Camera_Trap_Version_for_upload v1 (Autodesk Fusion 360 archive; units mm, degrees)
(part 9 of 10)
create_component "CreateComponent7"
create_component "CreateComponent2"
create_component "CreateComponent15"
create_component "CreateComponent3"
create_component "CreateComponent1"
create_component "CreateComponent16"
create_component "CreateComponent8"
create_component "CreateComponent17"
remove_body "RemoveBody4"
create_component "CreateComponent2"
create_component "CreateComponent9"
create_component "CreateComponent4"
create_component "CreateComponent10"
create_component "CreateComponent24"
create_component "CreateComponent25"
create_component "CreateComponent26" sketch "Sketch6"
create_component "CreateComponent27"
create_component "CreateComponent28"
create_component "CreateComponent29"
create_component "CreateComponent30"
create_component "CreateComponent31"
create_component "CreateComponent32"
create_component "CreateComponent33"
create_component "CreateComponent34"
create_component "CreateComponent35"
create_component "CreateComponent36"
create_component "CreateComponent37"
create_component "CreateComponent38"
create_component "CreateComponent39"
create_component "CreateComponent40"
create_component "CreateComponent41"
create_component "CreateComponent42"
create_component "CreateComponent43"
create_component "CreateComponent44"
create_component "CreateComponent45"
create_component "CreateComponent46"
create_component "CreateComponent47"
remove_body "RemoveBody1"
remove_body "RemoveBody2"
remove_body "RemoveBody3"
remove_body "RemoveBody4"
remove_body "RemoveBody5"
remove_body "RemoveBody6"
remove_body "RemoveBody7"
remove_body "RemoveBody8"
remove_body "RemoveBody1"
remove_body "RemoveBody2"
remove_body "RemoveBody3"
remove_body "RemoveBody4"
remove_body "RemoveBody1"
remove_body "RemoveBody1"
remove_body "RemoveBody1"
remove_body "RemoveBody1"
remove_body "RemoveBody1"
remove_body "RemoveBody1"
remove_body "RemoveBody1"
remove_body "RemoveBody1"
remove_body "RemoveBody1"
remove_body "RemoveBody1"
remove_body "RemoveBody1"
create_component "CreateComponent1"
create_component "CreateComponent3"
create_component "CreateComponent49"
create_component "CreateComponent50"
create_component "CreateComponent51"
create_component "CreateComponent52"
create_component "CreateComponent53"
create_component "CreateComponent54"
create_component "CreateComponent55"
create_component "CreateComponent1"
create_component "CreateComponent1"
create_component "CreateComponent2"
create_component "CreateComponent2"
remove_body "RemoveBody1"
create_component "CreateComponent7"
remove_body "RemoveBody2"
create_component "CreateComponent8"
remove_body "RemoveBody3"
create_component "CreateComponent9"
remove_body "RemoveBody4"
create_component "CreateComponent10"
remove_body "RemoveBody5"
remove_body "RemoveBody1"
remove_body "RemoveBody3"
remove_body "RemoveBody1"
remove_body "RemoveBody2"
remove_body "RemoveBody6"
remove_body "RemoveBody2"
create_component "CreateComponent1"
create_component "CreateComponent18"
create_component "CreateComponent9"
create_component "CreateComponent11"
create_component "CreateComponent1"
create_component "CreateComponent2"
remove_body "RemoveBody2"
create_component "CreateComponent13"
create_component "CreateComponent19"
create_component "CreateComponent1"
create_component "CreateComponent56"
remove_body "RemoveBody5"
extrude "Extrude22" cut sketch "Sketch33" profile of C1 C2 C3 C4 against normal blind 9
create_component "CreateComponent2"
create_component "CreateComponent3"
create_component "CreateComponent1"
create_component "CreateComponent5"
create_component "CreateComponent1"
create_component "CreateComponent6"
remove_instance "RemoveInstance1"
named bodies: "Ball_holder", "Screw", "Nut", "Lower_gear", "Mid_gear", "S1_L_Pin", "S1_L_Pin_cutting_tool", "Coupling_testing", "Gear_Holder_Coupling", "S1_paper_holder", "L_ball_bearing", "Right_ball_bearing", "Motor_End", "Motor_sleeve", "348", "340", "342", "344", "343", "interior_motor_holder", "exterior_motor_holder", "upper_pin", "lower_pin", "S2_L_Pin", "S3_L_Pin", "Hanger", "Distance_Test", "Roll_holder", "Roll_holder_34", "Roll_holder_32", "Gear_roll_holder", "Roll_holder_R", "Handle_assembled", "nut_test", "Left_Wall_Cap_Low", "Old_Left_Wall_Cap_Lower", "Left_Wall_Cap_Mid", "Extrusion_Wall", "Extrusion_hole Mid", "Extrusion_hold_Upper", "Front_wall", "OLD_new_below_Lef_Wall_Cap_Upper", "Restraining_Cap", "Sliding_cap", "Motor_holder_base", "Motor_holder_wing", "Left_Wall_Cap_Low (1)", "Right_Wall_Cap_Low (1)", "Handle_Exterior", "Coil", "Cutter_LU_Wall_Cap_", "Cutter_sliding_cap", "Cutter_LL_Wall_Cap", "Motor_test_wall", "Cutter_exterior", "Cutter_interior", "Roof", "Left_wall", "Back_wall", "Right_wall"

design "MicroSD Reader Assembly"
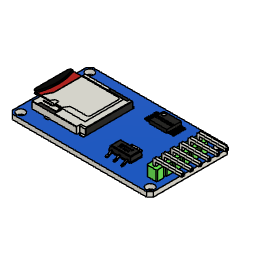
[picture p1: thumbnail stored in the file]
description: Part Number
part number: MicroSD Reader Assembly
part number: sdreader
part number: AMS1117
part number: card sd
base_feature "Base Feature1"
base_feature "Base Feature1"
base_feature "Base Feature1"
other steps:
create_component "CreateComponent1"
create_component "CreateComponent2"
create_component "CreateComponent3"

design "Gears_Motor2" references "9Vcell", "DHT11 module", "Button_Board_II", "Half_Bridge"
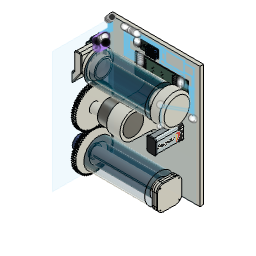
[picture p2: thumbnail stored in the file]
parameter "small_cons_line" = 45
parameter "large_cons_line" = 165
parameter "Roll_Inner_R" = 30
parameter "Roll_Outer_R" = 48
parameter "Roll_length" = 100
parameter "Motor_shaft" = 6
parameter "tube_ball_b" = 8
parameter "Extrusion_ball_b" = 16
parameter "Roll_Holder_major" = 30
parameter "Roll_Holder_minor" = 25
parameter "Holder_rod_bearing" = 8
sketch "Sketch1" plane through (0, 0, 0) normal (1, 0, 0) x axis (0, 1, 0)
sketch "Sketch1" plane through (0, 0, 0) normal (1, 0, 0) x axis (0, 1, 0)
  line L1 (0, 165) -> (0, 0)
  line L2 (0, 45) -> (0, 0)
  point P1 (0, 0)
  point P2 (0, 0)
  point P4 (0, 0)
  point P3 (0, 165)
  point P5 (0, 45)
  coincident P1 P2
  vertical L1
  coincident P1 P4
  parallel L1 L2
  dimension "d1" distance P2 P3 = 165 (= "large_cons_line")
  dimension "d2" distance P4 P5 = 45 (= "small_cons_line")
sketch "Sketch1" plane through (0, 0, 0) normal (1, 0, 0) x axis (0, 1, 0)
  line L1 (0, 105) -> (0, 45)
  line L2 (-11.6, 105) -> (-5.9, 105)
  circle C1 centre (0, 45) radius 24
  circle C2 centre (0, 45) radius 15
  circle C3 centre (0, 165) radius 15
  circle C4 centre (0, 165) radius 24
  circle C5 centre (0, 105) radius 3
  circle C6 centre (0, 105) radius 5.9
  circle C7 centre (0, 165) radius 30
  circle C8 centre (0, 45) radius 30
  circle C9 centre (6.8, 105) radius 18.4
  circle C10 centre (6.8, 105) radius 16.9
  circle C11 centre (0, 105) radius 30
  circle C12 centre (0, 105) radius 8
  point P3 (0, 45)
  point P6 (0, 45)
  point P7 (0, 105)
  point P8 (0, 105)
  point P12 (-5.9, 105)
  point P13 (-11.6, 105)
  concentric C1 C2
  concentric C3 C4
  coincident P3 P6
  vertical L1
  coincident P7 P8
  concentric C5 C6
  concentric C3 C7
  concentric C2 C8
  coincident C6 P12
  horizontal L2
  coincident P13 C9
  concentric C9 C10
  concentric C6 C11
  concentric C5 C12
  dimension "d7" diameter C1 = 48 (= "Roll_Outer_R")
  dimension "d8" diameter C2 = 30 (= "Roll_Inner_R")
  dimension "d9" diameter C3 = 30 (= "Roll_Inner_R")
  dimension "d10" diameter C4 = 48 (= "Roll_Outer_R")
  dimension "d14" distance P6 P7 = 60
  dimension "d16" diameter C5 = 6 (= "Motor_shaft")
  dimension "d17" diameter C6 = 11.8
  dimension "d18" diameter C7 = 60
  dimension "d20" diameter C8 = 60
  dimension "d22" distance P12 P13 = 5.7
  dimension "d23" diameter C9 = 36.8
  dimension "d24" diameter C10 = 33.8
  dimension "d25" diameter C11 = 60
  dimension "d120" diameter C12 = 16
extrude "Extrude1" new body sketch "Sketch1" profile of C1 C2 C3 C4 along normal blind 100 bodies "Lower_Roll", "Upper_Roll"
extrude "Extrude2" new body sketch "Sketch1" profile of C5 along normal blind 13 bodies "Motor_Shaft"
extrude "Extrude3" new body sketch "Sketch1" profile of C5 C6 blind 4 from offset 13 bodies "Shaft_Base"
extrude "Extrude4" new body sketch "Sketch1" profile of C6 C9 C10 blind 18 from offset 17 bodies "Motor_Gear_Box"
extrude "Extrude5" new body sketch "Sketch1" profile of C5 C6 C10 blind 22.5 from offset 35 bodies "Motor_End"
combine "Combine1" bodies "Motor"
sketch "Gear_teeth" plane through (0, 0, 0) normal (0, 0, 1) x axis (1, 0, 0)
  curve K1 (31.9963, -0.4887) -> (29.9991, -0.9267)
  curve K2 (31.9963, 0.4887) -> (29.9991, 0.9267)
  curve K3 (29.9991, -0.9267) -> (29.9983, -0.9266)
  curve K4 (29.9991, 0.9267) -> (29.9983, 0.9266)
  line L1 (29.9983, -0.9266) -> (0, 0)
  line L2 (29.9983, 0.9266) -> (0, 0)
  line L3 (0, 0) -> (0, 0)
  line L4 (0, 0) -> (0, 0)
  arc A1 centre (0, 0) radius 32 clockwise from (31.9963, 0.4887) to (31.9963, -0.4887)
sketch "Gear_Circle" plane through (0, 0, 0) normal (0, 0, 1) x axis (1, 0, 0)
  circle C1 centre (0, 0) radius 29.75
  circle C2 centre (0, 0) radius 8
  circle C3 centre (0, 0) radius 4
  circle C4 centre (0, 0) radius 6
  circle C5 centre (0, 0) radius 11
  concentric C1 C2
  concentric C2 C3
  concentric C1 C4
  concentric C2 C5
  dimension "d121" diameter C2 = 16
  dimension "d154" diameter C3 = 8 (= "tube_ball_b")
  dimension "d157" diameter C4 = 12
  dimension "d158" diameter C5 = 22
extrude "Extrude1" new body sketch "Gear_Circle" profile of C1 along normal blind 3 bodies "Motor_Coupling"
sweep "Sweep1" sketch "Gear_teeth" TwistAngle 1.5 TaperAngle 0
circular_pattern "C-Pattern1" countU 62 TotalAngle 360
combine "Combine1"
work_plane "WorkPlane1" AlongDistance 3
mirror "Mirror1" mirrorStitchTolerance 0.01
combine "Combine2"
sketch "Gear_Label" plane through (0, 0, 0) normal (0, 0, 1) x axis (1, 0, 0)
  curve K1 (83.1636, 0) -> (0, 0)
  curve K2 (83.1636, 3) -> (83.1636, 0)
  curve K3 (0, 3) -> (83.1636, 3)
  curve K4 (0, 0) -> (0, 3)
  perpendicular K1 K2
  parallel K1 K3
  parallel K2 K4
sketch "Gear_teeth" plane through (0, 0, 0) normal (0, 0, 1) x axis (1, 0, 0)
  curve K1 (31.9963, -0.4887) -> (29.9991, -0.9267)
  curve K2 (31.9963, 0.4887) -> (29.9991, 0.9267)
  curve K3 (29.9991, -0.9267) -> (29.9983, -0.9266)
  curve K4 (29.9991, 0.9267) -> (29.9983, 0.9266)
  line L1 (29.9983, -0.9266) -> (0, 0)
  line L2 (29.9983, 0.9266) -> (0, 0)
  line L3 (0, 0) -> (0, 0)
  line L4 (0, 0) -> (0, 0)
  arc A1 centre (0, 0) radius 32 clockwise from (31.9963, 0.4887) to (31.9963, -0.4887)
sketch "Gear_Circle" plane through (0, 0, 0) normal (0, 0, 1) x axis (1, 0, 0)
  circle C1 centre (0, 0) radius 29.75
  circle C2 centre (0, 0) radius 6
  circle C3 centre (0, 0) radius 15
  circle C4 centre (0, 0) radius 12.5
  circle C5 centre (0, 0) radius 20
  concentric C1 C2
  concentric C2 C3
  concentric C1 C4
  concentric C1 C5
  dimension "d102" diameter C2 = 12
  dimension "d115" diameter C3 = 30 (= "Roll_Holder_major")
  dimension "d117" diameter C4 = 25 (= "Roll_Holder_minor")
extrude "Extrude1" new body sketch "Gear_Circle" profile of C1 along normal blind 3 named "d89_1" bodies "Upper_Gear"
sweep "Sweep1" sketch "Gear_teeth" TwistAngle 1.5 named "d95_1" TaperAngle 0 named "d96_1"
circular_pattern "C-Pattern1" countU 62 named "d97_1" TotalAngle 360 named "d98_1"
combine "Combine1"
work_plane "WorkPlane1" AlongDistance 3 named "d99_1"
mirror "Mirror1" mirrorStitchTolerance 0.01 named "d101_1"
combine "Combine2"
sketch "Gear_Label" plane through (0, 0, 0) normal (0, 0, 1) x axis (1, 0, 0)
  curve K1 (83.1636, 0) -> (0, 0)
  curve K2 (83.1636, 3) -> (83.1636, 0)
  curve K3 (0, 3) -> (83.1636, 3)
  curve K4 (0, 0) -> (0, 3)
  perpendicular K1 K2
  parallel K1 K3
  parallel K2 K4
sketch "Sketch1" plane through (0, 0, 0) normal (0, 0, 1) x axis (1, 0, 0)
  curve K1 (31.9963, -0.4887) -> (29.9991, -0.9267)
  curve K2 (31.9963, 0.4887) -> (29.9991, 0.9267)
  curve K3 (29.9991, -0.9267) -> (29.9983, -0.9266)
  curve K4 (29.9991, 0.9267) -> (29.9983, 0.9266)
  line L1 (29.9983, -0.9266) -> (0, 0)
  line L2 (29.9983, 0.9266) -> (0, 0)
  line L3 (0, 0) -> (0, 0)
  line L4 (0, 0) -> (0, 0)
  arc A1 centre (0, 0) radius 32 clockwise from (31.9963, 0.4887) to (31.9963, -0.4887)
sketch "Sketch2" plane through (0, 0, 0) normal (0, 0, 1) x axis (1, 0, 0)
  circle C1 centre (0, 0) radius 29.75
  circle C2 centre (0, 0) radius 10
  circle C3 centre (0, 0) radius 4
  circle C4 centre (0, 0) radius 11
  concentric C1 C2
  concentric C2 C3
  concentric C2 C4
  dimension "d126" diameter C2 = 20
  dimension "d151" diameter C3 = 8
  dimension "d162" diameter C4 = 22
extrude "Extrude1" new body sketch "Sketch2" profile of C1 along normal blind 3 named "d89_2" bodies "Upper_Gear"
sweep "Sweep1" sketch "Sketch1" TwistAngle 1.5 named "d95_2" TaperAngle 0 named "d96_2"
circular_pattern "C-Pattern1" countU 62 named "d97_2" TotalAngle 360 named "d98_2"
combine "Combine1"
work_plane "WorkPlane1" AlongDistance 3 named "d99_2"
mirror "Mirror1" mirrorStitchTolerance 0.01 named "d101_2"
combine "Combine2"
sketch "Sketch3" plane through (0, 0, 0) normal (0, 0, 1) x axis (1, 0, 0)
  curve K1 (83.1636, 0) -> (0, 0)
  curve K2 (83.1636, 3) -> (83.1636, 0)
  curve K3 (0, 3) -> (83.1636, 3)
  curve K4 (0, 0) -> (0, 3)
  perpendicular K1 K2
  parallel K1 K3
  parallel K2 K4
extrude "Extrude2" new body sketch "Gear_Circle" profile of C2 along a picked direction blind 8 bodies "Nut_stopper_L"
position "Position1"
sketch "Sketch4" plane through (0, 0, 8) normal (0, 0, 1) x axis (-1, 0, 0)
  circle C1 centre (0, 0) radius 6
  circle C2 centre (0, 0) radius 4
  circle C3 centre (0, 0) radius 11
  circle C4 centre (0, 0) radius 4
  point P1 (0, 0)
  point P3 (0, 0)
  coincident P1 P3
  concentric C2 C3
  concentric C2 C4
  dimension "d105" diameter C2 = 8 (= "tube_ball_b")
  dimension "d110" diameter C3 = 22
  dimension "d111" diameter C4 = 8
extrude "Extrude3" new body sketch "Sketch4" profile of C2 C4 along a picked direction blind 16 (= "Extrusion_ball_b") bodies "Gear_cylinder_L"
extrude "Extrude4" new body sketch "Sketch4" along a picked direction blind 7 bodies "Ball_Bearing_L"
extrude "Extrude5" new body sketch "Gear_Circle" profile of C3 C4 along a picked direction blind -10 from offset -5 bodies "Cilinder_holder_L"
position "Position2"
extrude "Extrude2" add sketch "Gear_Circle" profile of C2 C3 C4 along a picked direction blind -16.5
combine "Combine4"
extrude "Extrude6" new body sketch "Gear_Circle" profile of C2 C3 C4 C5 along a picked direction blind -7 bodies "Cilinder_stopper_L"
move "Move1"
sketch "Sketch2" plane through (0, 0, 0) normal (0, 1, 0) x axis (0, 0, 1)
extrude "Extrude2" new body sketch "Sketch2" profile of C2 along a picked direction blind -2 bodies "Base"
sketch "Profile_bar_upper_axes" plane through (0, 0, 0) normal (0, 1, 0) x axis (1, 0, 0)
  line L1 (5, -157) -> (5, -177)
  line L2 (3, -177) -> (3, -157)
  line L3 (5, -177) -> (3, -177)
  line L4 (5, -157) -> (3, -157)
  line L5 (5, -167) -> (106, -167)
  line L6 (116, -167) -> (5, -167)
  line L7 (116, -159) -> (116, -167)
  line L8 (5, -159) -> (116, -159)
  line L9 (5, -159) -> (5, -167)
  line L10 (111, -168) -> (10, -168)
  line L11 (111, -166) -> (111, -168)
  line L12 (10, -166) -> (111, -166)
  line L13 (10, -168) -> (10, -166)
  point P6 (5, -167)
  point P10 (5, -159)
  point P8 (116, -167)
  point P11 (10, -168)
  point P12 (111, -168)
  midpoint L1 P6
  perpendicular L1 L6
  perpendicular L6 L7
  coincident L1 P10
  perpendicular L1 L8
  horizontal L10
  vertical L11
  horizontal L12
  vertical L13
  dimension "d141" distance P6 P8 = 111
  dimension "d143" distance P11 P12 = 101
revolve "Revolve2" sketch "Profile_bar_upper_axes" AlongAngle 360 bodies "Tape_holder"
extrude "Extrude2" new body sketch "Profile_bar_upper_axes" profile of L6 L10 L11 L12 L13 distance 10 bodies "Cutter_slit"
combine "Combine4"
move "Move2"
sketch "Sketch5" plane through (0, 0, -107) normal (0, 0, -1) x axis (1, 0, 0)
  circle C1 centre (2, 0) radius 15
  circle C2 centre (2, 0) radius 24
sketch "Sketch3" plane through (116, 0, 0) normal (1, 0, 0) x axis (0, 1, 0)
  circle C1 centre (0, 167) radius 8
  circle C2 centre (0, 167.5) radius 4
  dimension "d148" diameter C2 = 8 (= "Holder_rod_bearing")
extrude "Extrude3" add sketch "Sketch3" profile of C2 along normal blind 8
move "Move3"
sketch "Sketch4" plane through (116, 0, 0) normal (1, 0, 0) x axis (0, 1, 0)
  circle C1 centre (0, 167.5) radius 4
  circle C2 centre (0, 167) radius 8
extrude "Extrude4" new body sketch "Sketch2" profile of C3 along a picked direction blind 24 bodies "Gear_tube"
extrude "Extrude3" new body sketch "Gear_Circle" profile of C3 along normal blind 24 bodies "Gear_Tube"
extrude "Extrude4" new body sketch "Gear_Circle" profile of C2 C3 C4 C5 blind 7 from offset 17 bodies "Nut"
extrude "Extrude5" new body sketch "Sketch2" profile of C2 C3 C4 along a picked direction blind 7 from offset 17 bodies "Nut_L"
extrude "Extrude6" new body sketch "Sketch2" profile of C2 C3 C4 along a picked direction blind -7 from offset -114 bodies "Nut_R"
extrude "Extrude7" new body sketch "Gear_Circle" profile of C3 C4 along a picked direction blind -10 from offset -97 bodies "Cilinder_holder_R"
sketch "Sketch6" plane through (0, 0, -107) normal (0, 0, -1) x axis (1, 0, 0)
  circle C1 centre (2, 0) radius 15
  circle C2 centre (2, 0) radius 24
  circle C3 centre (0, 0) radius 30
  point P1 (0, 0)
  point P3 (0, 0)
  coincident P1 P3
  dimension "d172" diameter C3 = 60
extrude "Extrude8" add sketch "Sketch6" along a picked direction blind 28
sketch "Sketch5" plane through (138, 0, 0) normal (1, 0, 0) x axis (0, 1, 0)
  circle C1 centre (0, 43) radius 30
sketch "Sketch8" plane through (3, 0, 167) normal (-1, 0, 0) x axis (0, 0, 1)
sketch "Sketch4" plane through (0, 0, -121) normal (0, 0, -1) x axis (1, 0, 0)
  line L1 (-10, -20) -> (10, -20)
  line L2 (-20, 10) -> (-20, -10)
  line L3 (10, 20) -> (-10, 20)
  line L4 (20, -10) -> (20, 10)
  line L5 (-20, 20) -> (20, -20)
  line L6 (20, 20) -> (-20, -20)
  line L7 (-15, 10) -> (-15, -10)
  line L8 (-10, -15) -> (10, -15)
  line L9 (15, -10) -> (15, 10)
  line L10 (10, 15) -> (-10, 15)
  line L11 (0, -24) -> (0, 30)
  circle C1 centre (0, 0) radius 4
  circle C2 centre (0, 0) radius 11
  arc A1 centre (-10, 10) radius 10 clockwise from (-20, 10) to (-10, 20)
  arc A2 centre (10, 10) radius 10 clockwise from (10, 20) to (20, 10)
  arc A3 centre (10, -10) radius 10 clockwise from (20, -10) to (10, -20)
  arc A4 centre (-10, -10) radius 10 clockwise from (-10, -20) to (-20, -10)
  arc A5 centre (-10, 10) radius 5 clockwise from (-15, 10) to (-10, 15)
  arc A6 centre (-10, -10) radius 5 clockwise from (-10, -15) to (-15, -10)
  arc A7 centre (10, -10) radius 5 clockwise from (15, -10) to (10, -15)
  arc A8 centre (10, 10) radius 5 clockwise from (10, 15) to (15, 10)
  circle C3 centre (-15.3852, 15.3852) radius 0.75
  circle C4 centre (15.3852, -15.3852) radius 0.75
  circle C5 centre (15.3852, 15.3852) radius 0.75
  circle C6 centre (-15.3852, -15.3852) radius 0.75
  point P7 (0, 0)
  point P1 (0, 0)
  point P5 (-20, 20)
  point P6 (20, 20)
  point P3 (20, -20)
  point P4 (-20, -20)
  point P32 (-15.3852, 15.3852)
  horizontal L1
  perpendicular L1 L2
  parallel L1 L3
  parallel L2 L4
  coincident L5 P7
  coincident L6 P7
  coincident P1 P7
  coincident P5 L3
  coincident P5 L2
  tangent L3 A1
  tangent L2 A1
  coincident P6 L3
  coincident P6 L4
  tangent L3 A2
  tangent L4 A2
  equal A1 A2
  coincident P3 L4
  coincident P3 L1
  tangent L4 A3
  tangent L1 A3
  equal A1 A3
  coincident P4 L1
  coincident P4 L2
  tangent L1 A4
  tangent L2 A4
  equal A1 A4
  coincident L5 P32
  symmetric L6 C3 C4
  perpendicular L1 L11
  symmetric C3 L11 C5
  symmetric C4 L11 C6
  dimension "d185" distance P5 P6 = 40
  dimension "d186" distance P4 P5 = 40
  dimension "d187" radius A1 = 10
  dimension "d188" = 5
  dimension "d189" diameter C3 = 1.5
extrude "Extrude8" new body sketch "Sketch4" profile of C1 C2 L1 L2 L3 L4 A1 A2 A3 A4 L10 A6 L7 L9 L8 A5 A7 A8 C3 C4 C5 C6 along a picked direction blind 2 bodies "Lid_outer"
extrude "Extrude9" new body sketch "Sketch4" profile of C2 L1 L2 L3 L4 A1 A2 A3 A4 L10 A6 L7 L9 L8 A5 A7 A8 C3 C4 C5 C6 along a picked direction blind -3.5 bodies "Lid_mid"
extrude "Extrude10" new body sketch "Sketch4" profile of C2 L1 L2 L3 L4 A1 A2 A3 A4 L10 A6 L7 L9 L8 A5 A7 A8 C3 C4 C5 C6 along a picked direction blind -3 from offset -3.5 bodies "Lid_Inner"
move "Move1"
move "Move2"
move "Move4"
move "Move3"
move "Move4"
position "Position3"
work_plane "WorkPlane1" AlongDistance 0
sketch "Sketch3" plane through (-19.6953, 0, 0) normal (-1, 0, 0) x axis (0, -1, 0)
  line L1 (50, 200) -> (-50, 200)
  line L2 (50, 0) -> (50, 200)
  line L3 (-50, 0) -> (50, 0)
  line L4 (-50, 200) -> (-50, 0)
  horizontal L1
  vertical L2
  horizontal L3
  vertical L4
extrude "Extrude1" new body sketch "Sketch3" against normal blind 7 bodies "Wall_L"
move "Move1"
move "Move5"
work_plane "WorkPlane2" AlongDistance 0
sketch "Sketch5" plane through (0, 0, -123) normal (0, 0, -1) x axis (-1, 0, 0)
  line L1 (161.7205, 51.2462) -> (161.7205, -48.7538)
  line L2 (-38.2795, 51.2462) -> (161.7205, 51.2462)
  line L3 (-38.2795, -48.7538) -> (-38.2795, 51.2462)
  line L4 (161.7205, -48.7538) -> (-38.2795, -48.7538)
  line L5 (161.7205, -48.7538) -> (-38.2795, -48.7538)
  line L6 (161.7205, 51.2462) -> (161.7205, -48.7538)
  line L7 (-38.2795, 51.2462) -> (161.7205, 51.2462)
  line L8 (-38.2795, -48.7538) -> (-38.2795, 51.2462)
  point P3 (161.7205, 51.2462)
  point P8 (161.7205, 51.2462)
  point P5 (-38.2795, -48.7538)
  point P6 (-38.2795, -48.7538)
  horizontal L5
  vertical L6
  horizontal L7
  vertical L8
  coincident P3 P8
  coincident P5 P6
work_plane "WorkPlane2" AlongDistance 0
sketch "Right_Wall" plane through (127.3047, 0, 0) normal (1, 0, 0) x axis (0, 1, 0)
  line L1 (50, 0) -> (-50, 0)
  line L2 (50, 200) -> (50, 0)
  line L3 (-50, 200) -> (50, 200)
  line L4 (-50, 0) -> (-50, 200)
  line L5 (50, 200) -> (-50, 200)
  line L6 (50, 0) -> (50, 200)
  line L7 (-50, 0) -> (50, 0)
  line L8 (-50, 200) -> (-50, 0)
  point P3 (50, 0)
  point P8 (50, 0)
  point P5 (-50, 200)
  point P6 (-50, 200)
  horizontal L5
  vertical L6
  horizontal L7
  vertical L8
  coincident P3 P8
  coincident P5 P6
extrude "Extrude2" new body sketch "Right_Wall" blind -7 from offset -0.5 bodies "Wall_R"
sketch "Sketch9" plane through (60.5, 6.8, 105) normal (1, 0, 0) x axis (0, 1, 0)
work_plane "WorkPlane1" AlongDistance 0
sketch "Sketch2" plane through (57.5, 0, 0) normal (1, 0, 0) x axis (0, 1, 0)
  line L1 (50, 0) -> (50, 200)
  line L2 (50, 200) -> (-50, 200)
  line L3 (-50, 200) -> (-50, 0)
  line L4 (-50, 0) -> (50, 0)
  line L5 (6.8, 130) -> (6.8, 105)
  line L6 (23.7, 105) -> (6.8, 105)
  line L7 (35.3818, 127.6278) -> (6.8, 126.9)
  line L8 (50, 200) -> (-50, 200)
  line L9 (50, 142.6229) -> (50, 200)
  line L10 (-50, 0) -> (50, 0)
  line L11 (-50, 200) -> (-50, 0)
  line L12 (35.3818, 82.3722) -> (6.8, 83.1)
  circle C1 centre (6.8, 105) radius 16.9
  circle C2 centre (6.8, 105) radius 21.9
  arc A1 centre (35, 142.6229) radius 15 clockwise from (50, 142.6229) to (35.3818, 127.6278)
  arc A2 centre (35, 67.3771) radius 15 clockwise from (35.3818, 82.3722) to (50, 67.3771)
  point P2 (6.8, 105)
  point P7 (6.8, 105)
  point P10 (6.8, 105)
  point P11 (23.7, 105)
  point P12 (6.8, 126.9)
  point P4 (50, 0)
  point P15 (50, 0)
  point P5 (-50, 200)
  point P13 (-50, 200)
  point P20 (6.8, 83.1)
  point P17 (35.3818, 127.6278)
  point P21 (35.3818, 82.3722)
  point P18 (50, 142.6229)
  point P23 (50, 67.3771)
  coincident P2 P7
  vertical L5
  coincident P2 P10
  coincident C1 P11
  perpendicular L5 L6
  coincident L5 P12
  coincident C2 P12
  horizontal L8
  vertical L9
  horizontal L10
  vertical L11
  coincident P4 P15
  coincident P5 P13
  coincident P15 L9
  tangent L7 A1
  tangent L9 A1
  symmetric L6 P12 P20
  symmetric L6 P17 P21
  symmetric L6 P18 P23
  symmetric L6 A1 A2
  dimension "d211" = 5
  dimension "d218" radius A1 = 15
extrude "Extrude6" new body sketch "Sketch2" profile of C1 L1 C2 L7 A1 L12 A2 against normal blind 22 bodies "Motor_holder"
sketch "Sketch10" plane through (60.5, 0, 0) normal (1, 0, 0) x axis (0, 1, 0)
work_plane "WorkPlane5" AlongDistance 0
sketch "Sketch6" plane through (0, 50, 0) normal (0, 1, 0) x axis (1, 0, 0)
  line L1 (119.8047, 0) -> (126.8047, 0)
  line L2 (119.8047, -200) -> (119.8047, 0)
  line L3 (126.8047, -200) -> (119.8047, -200)
  line L4 (-22.6953, -200) -> (-22.6953, 0)
  line L5 (-15.6953, -200) -> (-22.6953, -200)
  line L6 (-15.6953, 0) -> (-15.6953, -200)
  line L7 (-22.6953, 0) -> (-15.6953, 0)
  line L8 (-22.6953, -200) -> (126.8047, -200)
  line L9 (-22.6953, 0) -> (-22.6953, -200)
  line L10 (126.8047, 0) -> (-22.6953, 0)
  point P6 (-22.6953, 0)
  point P12 (-22.6953, 0)
  point P2 (126.8047, -200)
  point P10 (126.8047, -200)
  horizontal L8
  vertical L9
  horizontal L10
  coincident P6 P12
  coincident P2 P10
extrude "Extrude4" new body sketch "Sketch6" along normal blind 6 bodies "Wall_Back"
sketch "Sketch11" plane through (138, 0, 0) normal (1, 0, 0) x axis (0, 1, 0)
  line L1 (0, 13) -> (0, 73)
  line L2 (29.9333, 41) -> (0, 41)
  line L3 (-29.9333, 41) -> (0, 41)
  line L4 (0, 41) -> (0, 73)
  line L5 (0, 73) -> (0, 41)
  line L6 (-29.9333, 41) -> (0, 41)
  circle C1 centre (0, 43) radius 30
  point P3 (0, 73)
  point P4 (0, 13)
  point P5 (0, 41)
  point P6 (29.9333, 41)
  point P7 (-29.9333, 41)
  coincident C1 P3
  coincident C1 P4
  vertical L1
  coincident L1 P5
  coincident C1 P6
  perpendicular L1 L2
  coincident C1 P7
  perpendicular L1 L3
sketch "Sketch8" plane through (0, 0, -135) normal (0, 0, -1) x axis (1, 0, 0)
  line L1 (-21.7198, 3.5) -> (-3.5, 3.5)
  line L2 (-30, 3.5) -> (-29.7951, 3.5)
  line L3 (-3.5, 29.7951) -> (-3.5, 30)
  line L4 (-3.5, 3.5) -> (-3.5, 21.7198)
  line L5 (0, 30) -> (0, -30)
  line L6 (30, 0) -> (-30, 0)
  line L7 (21.7198, 3.5) -> (3.5, 3.5)
  line L8 (3.5, 3.5) -> (3.5, 21.7198)
  line L9 (-21.7198, -3.5) -> (-3.5, -3.5)
  line L10 (-3.5, -3.5) -> (-3.5, -21.7198)
  line L11 (3.5, -3.5) -> (3.5, -21.7198)
  line L12 (21.7198, -3.5) -> (3.5, -3.5)
  circle C1 centre (0, 0) radius 30
  circle C2 centre (0, 0) radius 30
  arc A1 centre (0, 0) radius 22 clockwise from (-21.7198, 3.5) to (-3.5, 21.7198)
  arc A2 centre (0, 0) radius 22 clockwise from (3.5, 21.7198) to (21.7198, 3.5)
  arc A3 centre (0, 0) radius 22 clockwise from (-3.5, -21.7198) to (-21.7198, -3.5)
  arc A4 centre (0, 0) radius 22 clockwise from (21.7198, -3.5) to (3.5, -21.7198)
  point P1 (0, 0)
  point P3 (0, 0)
  point P9 (-29.7951, 3.5)
  point P10 (-3.5, 21.7198)
  point P11 (-3.5, 29.7951)
  point P12 (0, -30)
  point P13 (0, 30)
  point P14 (-30, 0)
  point P15 (30, 0)
  point P5 (-3.5, 3.5)
  point P16 (3.5, 3.5)
  point P8 (-21.7198, 3.5)
  point P17 (21.7198, 3.5)
  point P18 (3.5, 21.7198)
  point P20 (-3.5, -3.5)
  point P21 (-21.7198, -3.5)
  point P22 (-3.5, -21.7198)
  point P25 (3.5, -3.5)
  point P26 (21.7198, -3.5)
  point P24 (3.5, -21.7198)
  coincident P1 P3
  concentric C2 A1
  coincident C1 P9
  collinear L1 L2
  coincident P10 L3
  coincident C1 P11
  collinear L3 L4
  coincident C2 P12
  coincident C2 P13
  vertical L5
  coincident C1 P14
  coincident C1 P15
  horizontal L6
  symmetric P5 L5 P16
  symmetric A1 L5 A2
  symmetric P8 L5 P17
  symmetric P10 L5 P18
  symmetric P5 L6 P20
  symmetric A1 L6 A3
  symmetric P8 L6 P21
  symmetric P10 L6 P22
  symmetric L5 P20 P25
  symmetric L5 P21 P26
  symmetric L5 P22 P24
  symmetric L5 A3 A4
extrude "Extrude10" cut sketch "Sketch8" profile of L2 L4 A1 L7 L8 A2 L9 L10 A3 L11 L12 A4 along a picked direction blind -5
fillet "Fillet1" radius 2
fillet "Fillet2" radius 2
fillet "Fillet3" radius 2
fillet "Fillet4" radius 3
component_insert "Component Insert1"
position "Position4"
sketch "Sketch7" plane through (119.8047, 0, 0) normal (-1, 0, 0) x axis (0, -1, 0)
  line L1 (50, 0) -> (-50, 0)
  line L2 (50, 200) -> (50, 0)
  line L3 (-50, 200) -> (50, 200)
  line L4 (-50, 0) -> (-50, 200)
  line L5 (12, 122.3488) -> (-23.6969, 122.3488)
  line L6 (12, 97.3488) -> (-23.6969, 97.3488)
  line L7 (-33.15, 112.1992) -> (-33.15, 112.1988)
  line L8 (-33.15, 112.1992) -> (-33.5303, 111.8188)
  line L9 (-33.5303, 118.8788) -> (-33.15, 118.4984)
  line L10 (-33.15, 118.4988) -> (-33.15, 118.4984)
  line L11 (-35.5352, 117.0705) -> (-35.5352, 117.0821)
  line L12 (-35.5352, 117.0821) -> (-33.5925, 117.0821)
  line L13 (-33.5693, 117.0705) -> (-33.5925, 117.0821)
  line L14 (-36.0303, 118.8788) -> (-33.5303, 118.8788)
  curve K1 (-36.5255, 116.9074) -> (-36.5182, 116.8651)
  line L15 (-35.5352, 117.0705) -> (-33.5693, 117.0705)
  line L16 (-35.5352, 113.6271) -> (-33.5693, 113.6271)
  curve K2 (-36.5255, 118.3836) -> (-36.0303, 118.8788)
  line L17 (-36.5255, 116.9095) -> (-36.5255, 116.9074)
  line L18 (-35.5352, 113.6155) -> (-35.5352, 113.6271)
  line L19 (-35.5352, 113.6155) -> (-33.5925, 113.6155)
  line L20 (-33.5925, 113.6155) -> (-33.5693, 113.6271)
  line L21 (-36.0303, 111.8188) -> (-33.5303, 111.8188)
  curve K3 (-36.5255, 116.8229) -> (-36.5182, 116.8651)
  curve K4 (-36.5182, 113.8325) -> (-36.5255, 113.8747)
  line L22 (-23.6969, 97.3488) -> (-32, 97.3488)
  line L23 (-23.6969, 122.3488) -> (-32, 122.3488)
  line L24 (-33, 121.3488) -> (-33, 118.3488)
  line L25 (-33, 107.3488) -> (-33, 112.3488)
  line L26 (-33, 101.3488) -> (-33, 98.3488)
  line L27 (13, 101.3488) -> (13, 118.3488)
  line L28 (13, 121.3488) -> (13, 118.3488)
  line L29 (13, 101.3488) -> (13, 98.3488)
  line L30 (-36.5255, 113.7902) -> (-36.5255, 113.7881)
  curve K5 (-36.0303, 111.8188) -> (-36.5255, 112.3141)
  line L31 (-33.15, 101.3488) -> (-33.15, 101.8488)
  line L32 (-33.15, 106.8488) -> (-33.15, 107.3488)
  line L33 (-36, 101.8488) -> (-36, 104.3488)
  line L34 (-36, 104.3488) -> (-36, 106.8488)
  line L35 (-33.15, 118.4988) -> (-33, 118.3488)
  line L36 (-33.15, 112.1988) -> (-33, 112.3488)
  line L37 (-36.5255, 116.9095) -> (-36.5255, 118.3836)
  line L38 (-36.5255, 113.8747) -> (-36.5255, 116.8229)
  line L39 (-36.5255, 112.3141) -> (-36.5255, 113.7881)
  line L40 (-33, 101.3488) -> (-33.15, 101.3488)
  line L41 (-33, 107.3488) -> (-33.15, 107.3488)
  line L42 (-33.15, 101.8488) -> (-36, 101.8488)
  line L43 (-33.15, 106.8488) -> (-36, 106.8488)
  line L44 (16.5221, 125) -> (-40, 125)
  line L45 (16.5221, 94.0285) -> (16.5221, 125)
  line L46 (-40, 94.0285) -> (16.5221, 94.0285)
  line L47 (-40, 125) -> (-40, 94.0285)
  line L48 (-44, 90.0285) -> (20.5221, 90.0285)
  line L49 (-44, 129) -> (-44, 90.0285)
  line L50 (20.5221, 129) -> (-44, 129)
  line L51 (20.5221, 90.0285) -> (20.5221, 129)
  closed curve K6 centre (-36.0304, 113.7903)
  arc A1 centre (12, 98.3488) radius 1 clockwise from (13, 98.3488) to (12, 97.3488)
  arc A2 centre (12, 121.3488) radius 1 clockwise from (12, 122.3488) to (13, 121.3488)
  arc A3 centre (-32, 121.3488) radius 1 clockwise from (-33, 121.3488) to (-32, 122.3488)
  arc A4 centre (-32, 98.3488) radius 1 clockwise from (-32, 97.3488) to (-33, 98.3488)
  horizontal L44
  vertical L45
  horizontal L46
  vertical L47
  dimension "d237" = -4
extrude "Extrude7" new body of existing geometry blind 7
extrude "Extrude5" add sketch "Sketch7" profile of L44 L45 L46 L47 L48 L51 L49 L50 along normal blind 18
fillet "Fillet1" radius 3
fillet "Fillet2" radius 3
fillet "Fillet3" radius 3
fillet "Fillet4" radius 3
component_insert "Component Insert2"
position "Position5"
sketch "Sketch12" plane through (-22.6953, 0, 0) normal (-1, 0, 0) x axis (0, -1, 0)
  line L1 (50, 0) -> (-50, 0)
  line L2 (50, 200) -> (50, 0)
  line L3 (-50, 200) -> (50, 200)
  line L4 (-50, 0) -> (-50, 200)
  line L5 (-10, 185) -> (-45, 185)
  line L6 (-10, 116) -> (-10, 185)
  line L7 (-45, 116) -> (-10, 116)
  line L8 (-45, 185) -> (-45, 116)
  horizontal L5
  vertical L6
  horizontal L7
  vertical L8
extrude "Extrude6" cut sketch "Sketch12" profile of L5 L6 L7 L8 against normal blind 5
component_insert "Component Insert3"
component_insert "Component Insert4"
position "Position6"
sketch "Sketch13" plane through (-22.6953, 0, 0) normal (-1, 0, 0) x axis (0, -1, 0)
  line L1 (-10, 116) -> (-10, 185)
  line L2 (-45, 116) -> (-10, 116)
  line L3 (-45, 185) -> (-45, 116)
  line L4 (-10, 185) -> (-45, 185)
  line L5 (50, 0) -> (-50, 0)
  line L6 (50, 200) -> (50, 0)
  line L7 (-50, 200) -> (50, 200)
  line L8 (-50, 0) -> (-50, 200)
  circle C1 centre (1.2462, 167.7205) radius 4
  circle C2 centre (1.2462, 167.7205) radius 11
move_face "MoveFace1"
position "Position7"
work_plane "WorkPlane3" AlongDistance 0
move "Move3"
move "Move6" TranslateX 125 TranslateY 0 TranslateZ 0
work_plane "WorkPlane2" AlongDistance 95
sketch "Sketch9" plane through (0, 0, -110) normal (0, 0, -1) x axis (-1, 0, 0)
  circle C1 centre (0, 0) radius 12.5
  circle C2 centre (0, 0) radius 15
extrude "Extrude11" new body sketch "Sketch6" profile of C1 along a picked direction blind 10
sketch "Sketch10" plane through (0, 0, -117) normal (0, 0, -1) x axis (1, 0, 0)
  circle C1 centre (2, 0) radius 15
  circle C2 centre (2, 0) radius 4
  concentric C1 C2
  dimension "d256" diameter C2 = 8
extrude "Extrude12" add sketch "Sketch10" profile of C2 along a picked direction blind 10
sketch "Sketch11" plane through (0, 0, -127) normal (0, 0, -1) x axis (1, 0, 0)
  circle C1 centre (2, 0) radius 4
work_plane "WorkPlane3" AlongDistance 0
sketch "Sketch14" plane through (0, 0, -127) normal (0, 0, -1) x axis (1, 0, 0)
  circle C1 centre (2, 0) radius 4
  circle C2 centre (2, 0) radius 11
  concentric C1 C2
  dimension "d262" diameter C2 = 22
extrude "Extrude13" new body sketch "Sketch14" along a picked direction blind -7 bodies "Ball_bearing_R"
sketch "Sketch15" plane through (0, 0, -127) normal (0, 0, -1) x axis (1, 0, 0)
  circle C1 centre (2, 0) radius 4
  circle C2 centre (2, 0) radius 25
  concentric C1 C2
  dimension "d265" diameter C2 = 50
extrude "Extrude14" new body sketch "Sketch15" along a picked direction blind 12 second side blind 7 bodies "Handle"
move "Move4" TranslateX -2 TranslateY 0 TranslateZ 92
move "Move5" TranslateX 0 TranslateY 0 TranslateZ -90
move "Move7" TranslateX -125 TranslateY 0 TranslateZ 0
move "Move8" TranslateX 0 TranslateY 0 TranslateZ 3
move "Move6" TranslateX 0 TranslateY 0 TranslateZ 1
move "Move2" TranslateX -5 TranslateY 0 TranslateZ 0
move "Move7" TranslateX 0 TranslateY 0 TranslateZ 3
fillet "Fillet6" radius 4
move "Move8" TranslateX 0 TranslateY 0 TranslateZ -1
move "Move9" TranslateX 0 TranslateY 0 TranslateZ 2
sketch "Line_p_plane" plane through (0, 0, 24) normal (0, 0, 1) x axis (-1, 0, 0)
  line L1 (4, 0) -> (-4, 0)
  circle C1 centre (0, 0) radius 4
  point P3 (-4, 0)
  point P4 (4, 0)
  coincident C1 P3
  coincident C1 P4
  horizontal L1
work_plane "WorkPlane5" RotateAngle 90
sketch "Bearing_holder" plane through (0, 0, 0) normal (0, 1, 0) x axis (1, 0, 0)
  line L1 (4, -24) -> (-4, -24)
  line L2 (4, -8) -> (-4, -8)
  line L3 (-4, -24) -> (-4, -8)
  line L4 (4, -24) -> (4, -8)
  line L5 (6, -10) -> (-6, -10)
  line L6 (6, -2) -> (-6, -2)
  line L7 (-6, -10) -> (-6, -2)
  line L8 (6, -10) -> (6, -2)
  line L9 (11, -17) -> (-11, -17)
  line L10 (11, -10) -> (-11, -10)
  line L11 (-11, -17) -> (-11, -10)
  line L12 (11, -17) -> (11, -10)
  line L13 (15, -11) -> (15, -17)
  line L14 (-11.3593, -8) -> (12, -8)
  line L15 (-33.5842, -23.6953) -> (-13.1424, -8.5874)
  line L16 (-20, -23.6953) -> (-33.5842, -23.6953)
  line L17 (-15.5299, -20.3916) -> (-17.5588, -21.8911)
  line L18 (12, -20) -> (-14.3411, -20)
  line L19 (-167.734, -30.6953) -> (32.266, -30.6953)
  line L20 (-167.734, -23.6953) -> (-167.734, -30.6953)
  line L21 (-167.734, -23.6953) -> (32.266, -23.6953)
  line L22 (32.266, -23.6953) -> (32.266, -30.6953)
  arc A1 centre (12, -11) radius 3 clockwise from (12, -8) to (15, -11)
  arc A2 centre (12, -17) radius 3 clockwise from (15, -17) to (12, -20)
  arc A3 centre (-11.3593, -11) radius 3 clockwise from (-13.1424, -8.5874) to (-11.3593, -8)
  arc A4 centre (-14.3411, -22) radius 2 clockwise from (-15.5299, -20.3916) to (-14.3411, -20)
  arc A5 centre (-16.9645, -22.6953) radius 1 clockwise from (-16.9645, -23.6953) to (-17.5588, -21.8911)
  point P15 (-20, -23.6953)
  perpendicular L7 L14
  perpendicular L13 L18
  parallel L15 L17
  tangent L13 A1
  tangent L14 A1
  tangent L18 A2
  tangent L13 A2
  equal A1 A2
  tangent L14 A3
  tangent L15 A3
  equal A1 A3
  tangent L18 A4
  tangent L17 A4
  coincident P15 L17
  tangent L17 A5
  dimension "d301" radius A1 = 3
  dimension "d302" radius A4 = 2
  dimension "d303" radius A5 = 1
extrude "Extrude15" new body sketch "Bearing_holder" profile of L2 L3 L4 L5 L7 L8 L9 L10 L11 L12 L13 L14 L15 L16 L17 L18 A1 A2 A3 A4 A5 L21 distance 13 bodies "Wall_hanger"
move "Move9" TranslateX 0 TranslateY 0 TranslateZ -5
fillet "Fillet7" radius 1
fillet "Fillet8" radius 1
position "Position8"
sketch "Sketch14" plane through (0, 50, 0) normal (0, -1, 0) x axis (1, 0, 0)
  line L1 (119.8047, 0) -> (-22.6953, 0)
  line L2 (-22.6953, 200) -> (119.8047, 200)
  line L3 (-22.6953, 0) -> (-22.6953, 200)
  line L4 (119.8047, 200) -> (119.8047, 0)
sketch "Sketch15" plane through (0, 50, 0) normal (0, -1, 0) x axis (1, 0, 0)
  line L1 (10, 192) -> (24, 186)
  line L2 (10, 199) -> (10, 192)
  vertical L2
sketch "Sketch16" plane through (0, 48.49, 0) normal (0, -1, 0) x axis (1, 0, 0)
  line L1 (108.14, 136.6) -> (21.66, 136.6)
  line L2 (108.14, 169.73) -> (108.14, 136.6)
  line L3 (21.66, 169.73) -> (108.14, 169.73)
  line L4 (21.66, 136.6) -> (21.66, 169.73)
  circle C1 centre (49.7432, 143.97) radius 0.66
  circle C2 centre (51.9276, 146.51) radius 0.66
  circle C3 centre (49.6924, 149.05) radius 0.66
  circle C4 centre (51.8768, 151.59) radius 0.66
  circle C5 centre (67.2692, 143.97) radius 0.66
  circle C6 centre (65.034, 146.51) radius 0.66
  circle C7 centre (67.2692, 149.05) radius 0.66
  circle C8 centre (64.9832, 151.59) radius 0.66
  circle C9 centre (49.6924, 154.13) radius 0.66
  circle C10 centre (51.9276, 156.7208) radius 0.66
  circle C11 centre (49.6924, 159.2608) radius 0.66
  circle C12 centre (51.9276, 161.6484) radius 0.66
  circle C13 centre (67.1676, 154.13) radius 0.66
  circle C14 centre (65.034, 156.6192) radius 0.66
  circle C15 centre (67.1676, 159.21) radius 0.66
  circle C16 centre (64.9324, 161.5976) radius 0.66
move "Move3" TranslateX -5 TranslateY 0 TranslateZ 0
move "Move5"
sketch "Wiring_BW" plane through (0, 50, 0) normal (0, -1, 0) x axis (1, 0, 0)
  line L1 (-22.6953, 200) -> (119.8047, 200)
  line L2 (-22.6953, 0) -> (-22.6953, 200)
  line L3 (119.8047, 0) -> (-22.6953, 0)
  line L4 (119.8047, 200) -> (119.8047, 0)
  line L5 (101.4889, 165) -> (95, 165)
  line L6 (117, 163) -> (95, 163)
  line L7 (117, 120) -> (117, 163)
  line L8 (109.8058, 160) -> (95, 160)
  line L9 (110, 158) -> (95, 158)
  line L10 (101.4889, 173) -> (101.4889, 165)
  line L11 (22.9578, 191.8543) -> (61.8816, 191.8543)
  line L12 (11, 167) -> (29, 167)
  line L13 (11, 195) -> (11, 167)
  line L14 (9, 164) -> (29, 164)
  line L15 (9, 195) -> (9, 164)
  line L16 (7, 161) -> (29, 161)
  line L17 (7, 195) -> (7, 161)
  line L18 (5, 158) -> (29, 158)
  line L19 (5, 195) -> (5, 158)
  line L20 (3, 155) -> (29.05, 155)
  line L21 (3, 195) -> (3, 155)
  line L22 (14, 181.5) -> (24, 181.5)
  line L23 (14, 195) -> (14, 181.5)
  line L24 (17, 183.5) -> (24, 183.5)
  line L25 (17, 195) -> (17, 183.5)
  line L26 (19, 185.5) -> (24, 185.5)
  line L27 (19, 195) -> (19, 185.5)
  line L28 (114.3, 161.53) -> (95, 161.53)
  line L29 (114.3, 120) -> (114.3, 161.53)
  line L30 (61.8816, 173) -> (101.4889, 173)
  line L31 (61.8816, 191.8543) -> (61.8816, 173)
  line L32 (101, 195) -> (70, 195)
  line L33 (101, 177) -> (101, 195)
  line L34 (70, 177) -> (101, 177)
  line L35 (70, 195) -> (70, 177)
  line L36 (114.3, 179) -> (114.3, 161.53)
  line L37 (101, 179) -> (114.3, 179)
  line L38 (117, 192) -> (117, 163)
  line L39 (101, 192) -> (117, 192)
  line L40 (25, 196.011) -> (67, 196.011)
  line L41 (67, 190) -> (67, 196.011)
  line L42 (70, 190) -> (67, 190)
  line L43 (64, 179) -> (70, 179)
  line L44 (64, 193.9253) -> (64, 179)
  line L45 (23, 193.9253) -> (64, 193.9253)
  line L46 (110, 135) -> (110, 158)
  line L47 (110, 130) -> (110, 135)
  line L48 (61.9071, 112.9584) -> (110, 130)
  line L49 (112.5385, 160) -> (109.8058, 160)
  line L50 (112.5385, 127.6578) -> (112.5385, 160)
  line L51 (62.4654, 109.9145) -> (112.5385, 127.6578)
  line L52 (62.4654, 82.9656) -> (62.4654, 109.9145)
  line L53 (21, 191.8543) -> (22.9578, 191.8543)
  line L54 (21, 195) -> (21, 191.8543)
  line L55 (23, 195) -> (23, 193.9253)
  point P51 (101, 179)
  point P53 (101, 192)
  point P57 (70, 190)
  point P58 (70, 179)
  point P46 (70, 195)
  point P49 (70, 177)
  perpendicular L4 L6
  perpendicular L5 L7
  perpendicular L5 L10
  perpendicular L2 L12
  perpendicular L12 L13
  perpendicular L13 L14
  perpendicular L11 L15
  perpendicular L2 L16
  perpendicular L16 L17
  perpendicular L17 L18
  perpendicular L18 L19
  perpendicular L19 L20
  perpendicular L18 L21
  horizontal L11
  perpendicular L13 L22
  perpendicular L22 L23
  perpendicular L23 L24
  perpendicular L11 L25
  perpendicular L25 L26
  perpendicular L11 L27
  parallel L8 L28
  perpendicular L8 L29
  vertical L29
  perpendicular L10 L30
  perpendicular L11 L31
  horizontal L32
  vertical L33
  horizontal L34
  vertical L35
  perpendicular L6 L36
  coincident L33 P51
  perpendicular L33 L37
  perpendicular L6 L38
  coincident L33 P53
  perpendicular L33 L39
  horizontal L40
  perpendicular L40 L41
  coincident L35 P57
  perpendicular L35 L42
  coincident L35 P58
  perpendicular L35 L43
  perpendicular L42 L44
  perpendicular L44 L45
  horizontal L9
  perpendicular L9 L46
  vertical L47
  perpendicular L29 L49
  perpendicular L49 L50
  parallel L48 L51
  perpendicular L49 L52
  parallel L11 L53
  perpendicular L53 L54
  perpendicular L45 L55
  dimension "d379" distance P46 P49 = 18
extrude "Extrude8" new body sketch "Wiring_BW" profile of L32 L33 L34 L35 along normal blind 6.5 bodies "Voltage_reductor"
sketch "Wiring_LW" plane through (-15.6953, 0, 0) normal (1, 0, 0) x axis (0, 1, 0)
  line L1 (50, 0) -> (-50, 0)
  line L2 (50, 200) -> (50, 0)
  line L3 (-50, 200) -> (50, 200)
  line L4 (-50, 0) -> (-50, 200)
  line L5 (34.7049, 177.7654) -> (37.6449, 177.7654)
  line L6 (37.6449, 168.9654) -> (37.6449, 177.7654)
  line L7 (34.7049, 168.9654) -> (37.6449, 168.9654)
  line L8 (32.1649, 177.7654) -> (35.1049, 177.7654)
  line L9 (32.1649, 168.9654) -> (35.1049, 168.9654)
  line L10 (29.6249, 177.7654) -> (32.5649, 177.7654)
  line L11 (29.6249, 168.9654) -> (32.5649, 168.9654)
  line L12 (27.0849, 177.7654) -> (30.0249, 177.7654)
  line L13 (27.0849, 168.9654) -> (30.0249, 168.9654)
  line L14 (24.5449, 177.7654) -> (27.4849, 177.7654)
  line L15 (24.5449, 168.9654) -> (27.4849, 168.9654)
  line L16 (22.0049, 177.7654) -> (24.9449, 177.7654)
  line L17 (22.0049, 168.9654) -> (22.0049, 177.7654)
  line L18 (22.0049, 168.9654) -> (24.9449, 168.9654)
  line L19 (37.6449, 177.7654) -> (22.0049, 177.7654)
  line L20 (37.6449, 168.9654) -> (37.6449, 177.7654)
  line L21 (22.0049, 168.9654) -> (37.6449, 168.9654)
  line L22 (22.0049, 177.7654) -> (22.0049, 168.9654)
  line L23 (42, 187) -> (28.5549, 187)
  line L24 (42, 200) -> (42, 187)
  line L25 (44, 184.9745) -> (31.0949, 184.9745)
  line L26 (44, 200) -> (44, 184.9745)
  line L27 (46, 183.077) -> (33.6349, 183.077)
  line L28 (46, 200) -> (46, 183.077)
  line L29 (48, 181) -> (36.4231, 181)
  line L30 (48, 200) -> (48, 181)
  line L31 (28.5549, 178) -> (28.5549, 187)
  line L32 (31.0949, 178) -> (31.0949, 184.9745)
  line L33 (33.6349, 178) -> (33.6349, 183.077)
  line L34 (36.4231, 178) -> (36.4231, 181)
  line L35 (37.6449, 177.7654) -> (22.0049, 177.7654)
  line L36 (37.6449, 168.9654) -> (37.6449, 177.7654)
  line L37 (22.0049, 168.9654) -> (37.6449, 168.9654)
  line L38 (22.0049, 177.7654) -> (22.0049, 168.9654)
  point P8 (37.6449, 168.9654)
  point P32 (37.6449, 168.9654)
  point P27 (22.0049, 177.7654)
  point P30 (22.0049, 177.7654)
  point P39 (42, 200)
  point P41 (44, 200)
  point P43 (46, 200)
  point P45 (48, 200)
  point P51 (37.6449, 168.9654)
  horizontal L19
  vertical L22
  coincident P8 P32
  coincident P27 P30
  coincident L3 P39
  perpendicular L3 L24
  coincident L3 P41
  perpendicular L3 L26
  coincident L3 P43
  perpendicular L3 L28
  coincident L3 P45
  perpendicular L3 L30
  perpendicular L19 L31
  perpendicular L25 L32
  perpendicular L27 L33
  perpendicular L19 L34
  horizontal L35
  vertical L36
  horizontal L37
  vertical L38
  coincident P8 P51
extrude "Extrude9" add sketch "Wiring_LW" profile of L5 L6 L7 L8 L9 L10 L11 L12 L13 L14 L15 L16 L17 L18 L19 L20 L21 L22 L35 L36 L37 L38 along normal blind 2
combine "Combine1"
form "Form1"
form "Form2"
combine "Combine1" bodies "Motor_End"
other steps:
create_component "CreateComponent1"
create_component "CreateComponent2"
create_component "CreateComponent1"
create_component "CreateComponent6"
create_component "CreateComponent7"
create_component "CreateComponent8"
create_component "CreateComponent9"
create_component "CreateComponent10"
named bodies: "Lower_Roll", "Upper_Roll", "Motor_Shaft", "Shaft_Base", "Motor_Gear_Box", "Motor_End", "Motor", "Motor_Coupling", "Upper_Gear", "Nut_stopper_L", "Gear_cylinder_L", "Ball_Bearing_L", "Cilinder_holder_L", "Cilinder_stopper_L", "Base", "Tape_holder", "Cutter_slit", "Gear_tube", "Gear_Tube", "Nut", "Nut_L", "Nut_R", "Cilinder_holder_R", "Lid_outer", "Lid_mid", "Lid_Inner", "Wall_L", "Wall_R", "Motor_holder", "Wall_Back", "Ball_bearing_R", "Handle", "Wall_hanger", "Voltage_reductor"

design "DHT11 module"
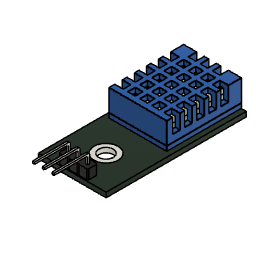
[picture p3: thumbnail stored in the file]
description: STEP AP214
part number: DHT11 module
base_feature "Base Feature"

design "Control" references "Button_Board_II", "DB_Updated", "1.3+Inch+OLED+Display", "MicroSD Reader Assembly"
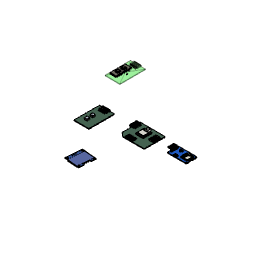
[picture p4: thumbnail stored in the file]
parameter "Base_extrusion" = 2
parameter "button_extrusion" = 4
parameter "cutter" = 1
base_mesh_feature "Base Mesh Feature"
